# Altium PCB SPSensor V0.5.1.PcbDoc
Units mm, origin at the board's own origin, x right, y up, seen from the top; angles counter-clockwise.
Board outline 22.01 x 74 mm, 4 copper layers (TopLayer, GND, PWR, BottomLayer); 82 components, 57 nets, 274 pads, 109 vias.
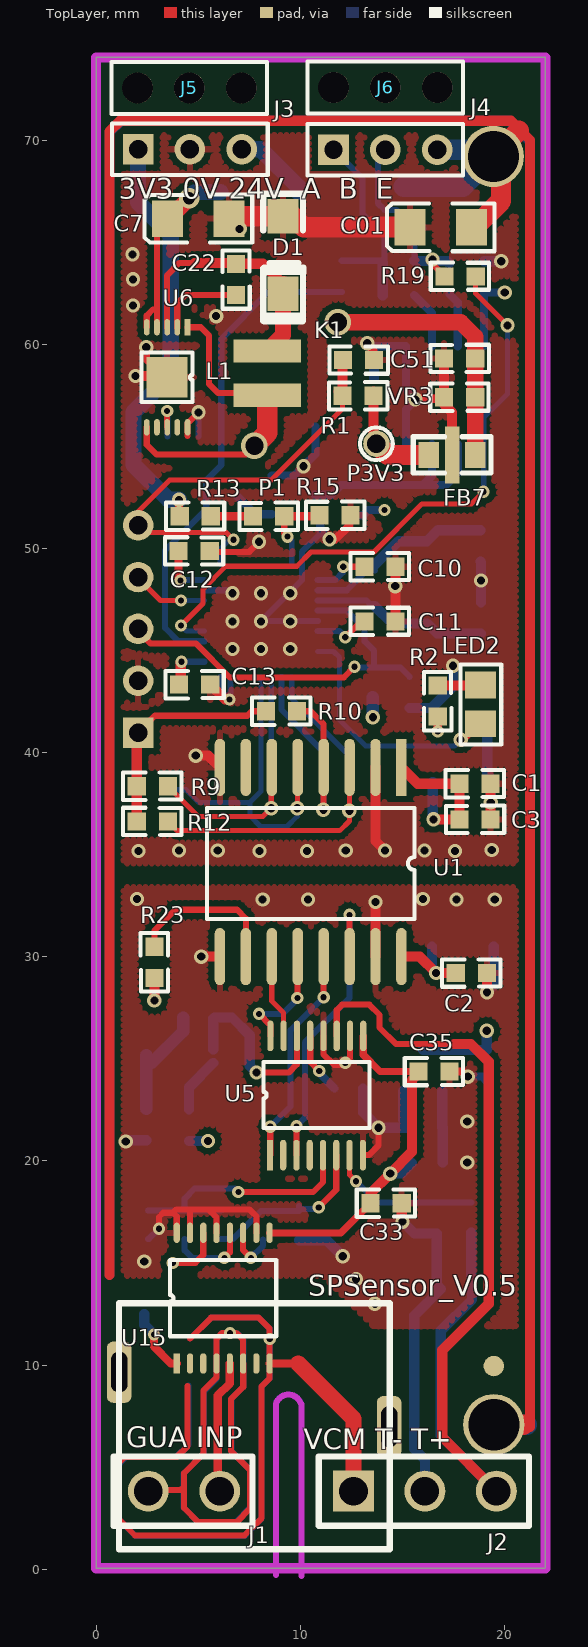
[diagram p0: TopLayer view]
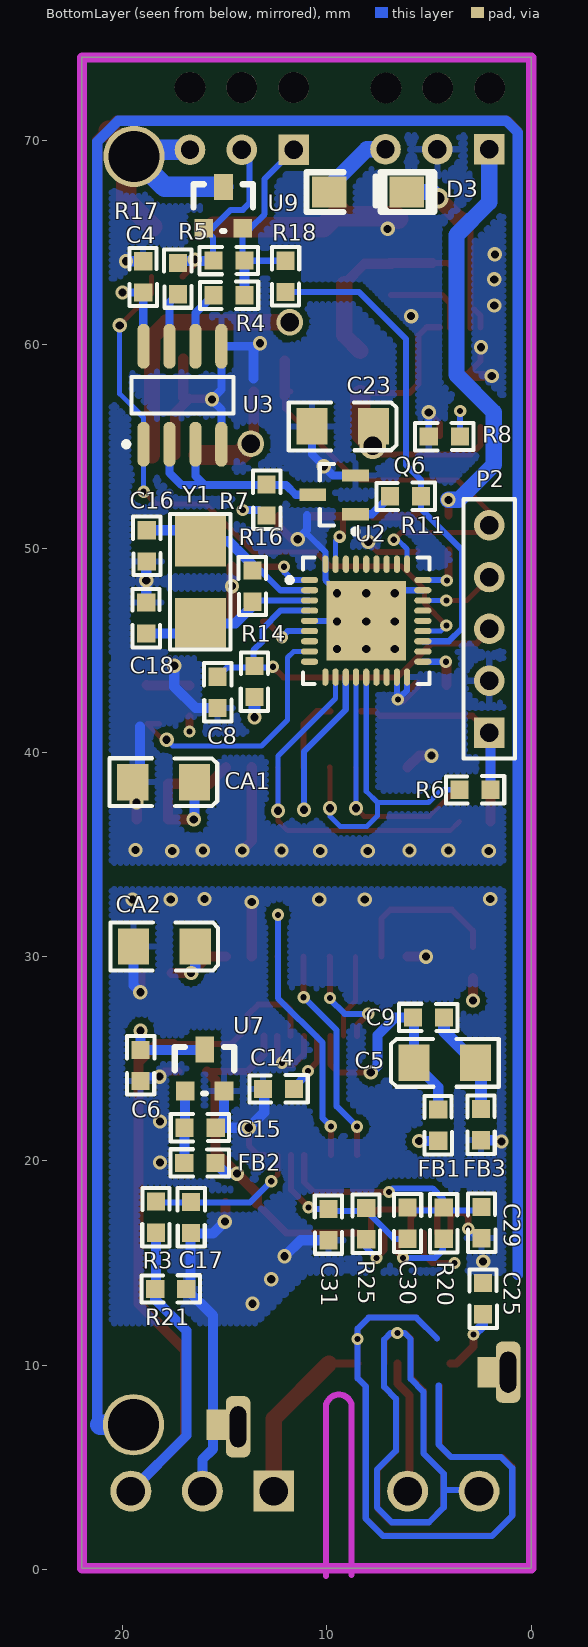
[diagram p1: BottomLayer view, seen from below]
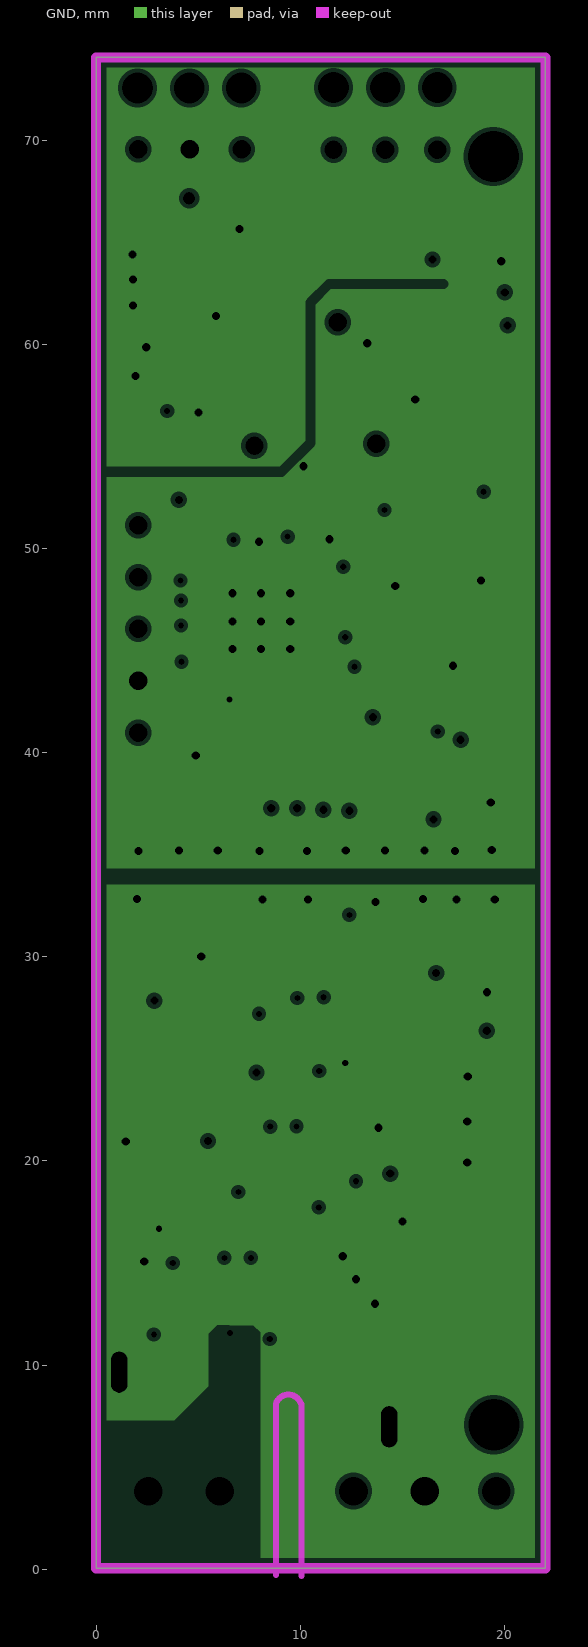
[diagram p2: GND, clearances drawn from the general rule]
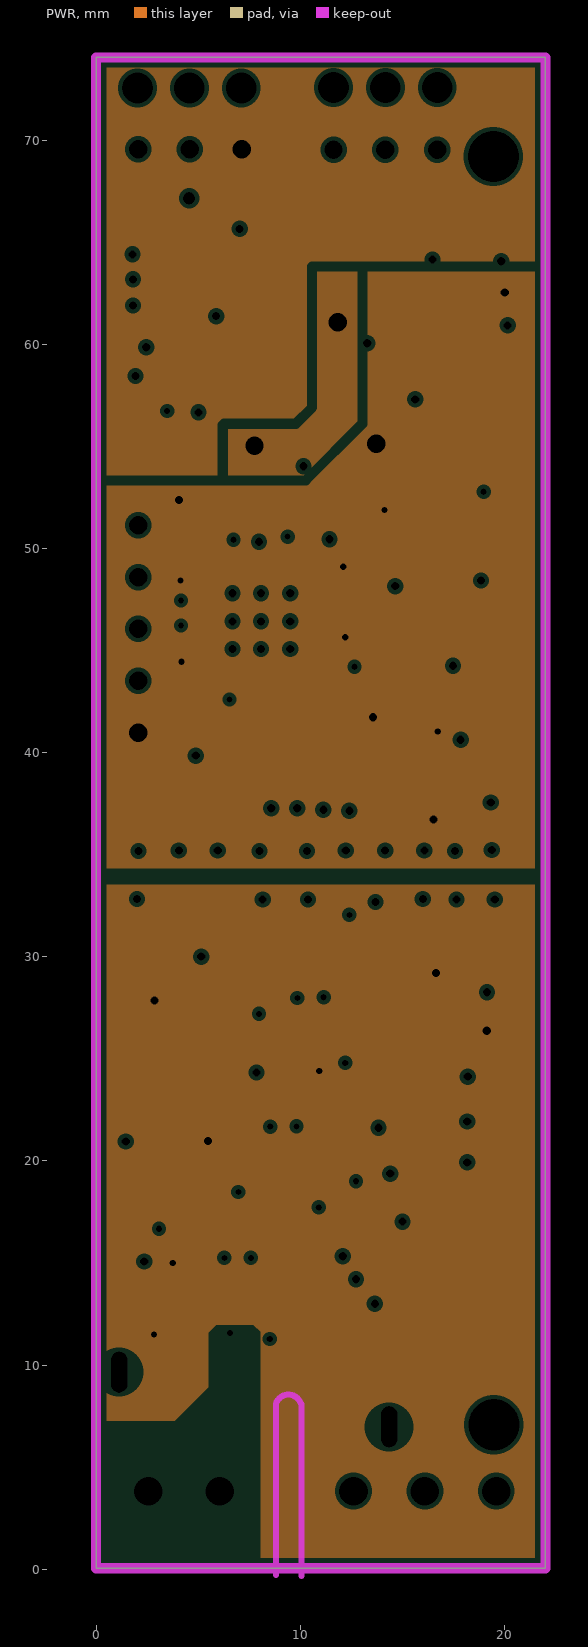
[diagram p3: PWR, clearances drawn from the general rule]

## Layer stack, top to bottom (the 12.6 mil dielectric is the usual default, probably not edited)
TopLayer: signal copper 0.0356
Dielectric: core 0.32, FR-4, Dk 4.8
GND: plane copper 0.0356, net (Multiple Nets)
Dielectric: prepreg 0.32, FR-4, Dk 4.8
PWR: plane copper 0.0356, net (Multiple Nets)
Dielectric: core 0.32, FR-4, Dk 4.8
BottomLayer: signal copper 0.0356

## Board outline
-0.006,0.05 22,0.05 22,74.05 -0.006,74.05

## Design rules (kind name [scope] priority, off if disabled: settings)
Clearance Clearance_poly [InPolygon] p1: gap=0.3
Clearance [All] p2: gap=0.15
ComponentClearance [All] p1: gap=0.15 collisioncheckmode=3 verticalgap=0.254 showdistances=FALSE
FabricationTestPointUsage TestPointUsage [All] p1: valid=0 allowmultiple=FALSE
FabricationTestpoint Testpoint [All] p1: side=3 testpointundercomponent=TRUE minsize=1.016 maxsize=2.54 preferedsize=1.524 minholesize=0.508 maxholesize=1.016 preferedholesize=0.813 testpointgrid=0.025 allowsidetop=TRUE allowsidebottom=TRUE usegrid=TRUE gridtolerance=0
HoleSize [All] p1: absolutevalues=TRUE maxlimit=10 minlimit=0.025 maxpercent=80.000 minpercent=20.000
MinimumSolderMaskSliver [All] p1: minsoldermaskwidth=0.15
PlaneClearance [All] p1: clearance=0.2
PlaneConnect [All] p1: planeconnectstyle=Relief reliefexpansion=0.3 reliefentries=4 reliefconductorwidth=0.3 reliefairgap=0.3
PolygonConnect PolygonConnect_via [IsVia] p1: connectstyle=Direct reliefconductorwidth=0.254 reliefentries=4 polygonreliefangle="90 Angle"
PolygonConnect [All] p2: connectstyle=Relief reliefconductorwidth=0.3 reliefentries=4 polygonreliefangle="90 Angle"
RoutingVias [All] p1: holewidth=0.305 width=0.61 viastyle="Through Hole" minholewidth=0.254 minwidth=0.508 maxholewidth=2 maxwidth=5
SilkToSilkClearance [All] p1: silktosilkclearance=0
SilkscreenOverComponentPads [All] p1: minsilkscreentomaskgap=0
SolderMaskExpansion [All] p1: expansion=0.102
Width [All] p1: maxlimit=5.08 minlimit=0.1 preferedwidth=0.254
19 further rules are at their usual default settings.

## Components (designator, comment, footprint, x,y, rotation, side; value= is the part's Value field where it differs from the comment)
C1 "10nF" SM0603 18.55,38.525 r0 top
C01 "1nF/2kV" SM1206 16.875,65.725 r180 top
C2 "0.1uF" SM0603 18.375,29.25 r0 top
C3 "0.1uF" SM0603 18.55,36.675 r180 top
C4 "0.1uF" SM0603 19.05,63.3 r90 bottom
C5 "10uF" SM1206 4.225,24.8 r0 bottom
C6 "4.7uF" SM0603 19.075,24.675 r270 bottom
C7 "4.7uF/50V" SM1206 5,66.15 r180 top
C8 "0.1uF" SM0603 15.3,42.95 r270 bottom
C9 "0.1uF" SM0603 5.025,27.075 r180 bottom
C10 "0.1uF" SM0603 13.9,49.15 r0 top
C11 "0.1uF" SM0603 13.9,46.475 r0 top
C12 "0.1uF" SM0603 4.8,49.925 r0 top
C13 "0.1uF" SM0603 4.825,43.375 r0 top
C14 "0.1uF" SM0603 12.375,23.475 r0 bottom
C15 "1uF" SM0603 16.21,21.675 r180 bottom
C16 "22pF" SM0603 18.775,50.125 r270 bottom
C17 "1uF" SM0603 16.6,17.225 r270 bottom
C18 "22pF" SM0603 18.9,46.59 r90 bottom
C22 "0.47uF" SM0603 6.8,63.175 r90 top
C23 "22uF" SM1206 9.225,55.975 r180 bottom
C25 "0.1uF" SM0603 2.4,13.25 r90 bottom
C29 "1uF" SM0603 2.475,16.975 r90 bottom
C30 "100pF" SM0603 6,16.95 r270 bottom
C31 "1uF" SM0603 9.875,16.875 r270 bottom
C33 "0.1uF" SM0603 14.2,17.975 r0 top
C35 "0.1uF" SM0603 16.55,24.425 r0 top
C51 "0.1uF" SM0603 17.8,59.25 r180 top
CA1 "10uF" SM1206 18,38.55 r180 bottom
CA2 "10uF" SM1206 17.96,30.5 r180 bottom
D1 "CD1607-B140" 1206D 9.15,66.075 r270 top
D3 "M7" 1206D 9.7,67.45 r180 bottom
FB1 "BLM18PG600SN1" SM0603 4.6,21.75 r90 bottom
FB2 "BLM18PG600SN1" SM0603 16.225,19.95 r180 bottom
FB3 "BLM18PG600SN1" SM0603 2.5,21.775 r90 bottom
FB7 "NFM21PC105B1C3" NFM21PC105 18.575,54.575 r180 top
J1 "Header 4" CON1x2-3.5mm 2.55,3.825 r0 top
J2 "Header 2" CON1x3-3.5mm 12.6,3.825 r0 top
J3 "Header 3" HDR1X3#1 2.05,69.55 r0 top
J4 "Header 3" HDR1X3#1 11.625,69.525 r0 top
J5 "Header 3" HDR1X3#2 2.025,72.55 r0 top
J6 "Header 3" HDR1X3#2 11.625,72.575 r0 top
K1 "KEY1" SM0603 12.85,59.175 r180 top (schematic designator R1)
L1 "LPS3010-472ML" LPS3010 8.375,59.666 r270 top
LED2 "RUN" SM0805 18.8,42.375 r270 top
P1 "NC" sm0603 8.45,51.525 r180 top
P2 "Header 5" HDR1X5 2.05,40.975 r90 bottom
P3V3 "TestPoint" "test point" 13.725,55.125 r90 top
Q6 "MMBT3904" SOT23_N 9.65,52.625 r0 bottom
R1 "10K" SM0603 12.825,57.425 r180 top
R2 "560R" SM0603 16.675,42.525 r90 top
R3 "10K" SM0603 18.425,17.24 r90 bottom
R4 "10R" SM0603 14.8,62.35 r0 bottom
R5 "120R" SM0603 14.8,64.15 r180 bottom
R6 "100K" SM0603 2.75,38.125 r0 bottom
R7 "4.7K" SM0603 12.9,52.375 r270 bottom
R8 "49.9K" SM0603 4.25,55.525 r180 bottom
R9 "100K" SM0603 2.75,38.4 r0 top
R10 "100K" SM0603 9.075,42.075 r0 top
R11 "1K" SM0603 6.15,52.5 r0 bottom
R12 "100K" SM0603 2.75,36.675 r0 top
R13 "1K" SM0603 4.85,51.625 r0 top
R14 "10K" SM0603 13.6,43.475 r90 bottom
R15 "100K" SM0603 11.7,51.575 r180 top
R16 "10M" SM0603 13.6,48.15 r270 bottom
R17 "10R" SM0603 17.25,63.21 r270 bottom
R18 "0R" SM0603 11.975,63.325 r270 bottom
R19 "0R" SM0603 17.825,63.375 r0 top
R20 "10K" SM0603 4.325,16.95 r90 bottom
R21 "NC" SM0603 17.65,13.675 r0 bottom
R23 "4.7K" SM0603 2.9,29.725 r270 top
R25 "10K" SM0603 8.125,16.925 r90 bottom
U1 "ADuM5401ARWZ" ADUM1401 14.95,39.275 r270 top
U2 "STM32F103T8U6" VFQN36_V 8.075,46.45 r180 bottom
U3 "MAX3485CSA" NSO8_N 17.075,57.5 r90 bottom
U5 "AD7793BRU" AD7793 10.795,23.2 r90 top
U6 "LT3971IMSE-3.3" LT3971 3.475,58.381 r180 top
U7 "AD1584BRTZ" SOT-23 14.614,25.575 r180 bottom
U9 "SM712.TCT" SOT-23 13.7,67.825 r180 bottom
U15 "LMP91200" LMP91200 6.219,13.275 r0 top
VR3 "V3.5MLA0603N" SM0603 17.8,57.45 r0 top (schematic designator VA2)
Y1 "8MHz" CY5.4X4.6 16.2,50.325 r270 bottom

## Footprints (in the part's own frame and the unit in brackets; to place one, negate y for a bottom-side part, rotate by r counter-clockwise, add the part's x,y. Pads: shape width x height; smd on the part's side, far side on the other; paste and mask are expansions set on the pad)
1206D [mm]
  rect 1.7x1.524 smd: 1(-0.19,0.003) 2(3.61,0.003)
  silkscreen extent -1.3,-0.97 4.96,0.99
AD7793 [mm]
  rect 1.5x0.3 smd: 1(-2.921,2.286)
  oval 1.5x0.3 smd: 2(-2.921,1.636) 3(-2.921,0.986) 4(-2.921,0.336) 5(-2.921,-0.314) 6(-2.921,-0.964) 7(-2.921,-1.614) 8(-2.921,-2.264) 9(2.921,-2.286) 10(2.921,-1.636) 11(2.921,-0.986) 12(2.921,-0.336) 13(2.921,0.314) 14(2.921,0.964) 15(2.921,1.614) 16(2.921,2.264)
  silkscreen extent -1.59,-2.59 1.64,2.61
ADUM1401 [mm]
  rect 2.8x0.51 smd: 1(0,0)
  oval 2.8x0.51 smd: 2(0,-1.27) 3(0,-2.54) 4(0,-3.81) 5(0,-5.08) 6(0,-6.35) 7(0,-7.62) 8(0,-8.89) 9(9.271,-8.89) 10(9.271,-7.62) 11(9.271,-6.35) 12(9.271,-5.08) 13(9.271,-3.81) 14(9.271,-2.54) 15(9.271,-1.27) 16(9.271,0)
  silkscreen extent 1.99,-9.53 7.43,0.64
CON1x2-3.5mm [mm]
  round 2 hole 1.4: 1(0,0) 2(3.5,0)
  silkscreen extent -1.7,-1.7 5.1,1.7
CON1x3-3.5mm [mm]
  rect 2x2 hole 1.4: 1(0,0)
  round 2 hole 1.4: 2(3.5,0) 3(7,0)
  silkscreen extent -1.7,-1.7 8.6,1.7
CY5.4X4.6 [mm]
  rect 2.5x2.5 smd: 1(-0.025,0) 2(4,0)
  silkscreen extent -1.35,-1.49 5.28,1.49
HDR1X3#1 [mm] "Connector; Header; 3 Position"
  rect 1.5x1.5 hole 0.9: 1(0,0)
  round 1.5 hole 0.9: 2(2.54,0) 3(5.08,0)
  silkscreen extent -1.27,-1.27 6.35,1.27
HDR1X3#2 [mm] "Connector; Header; 3 Position"
  round 1.5 hole 1.5: 1(0,0) 2(2.54,0) 3(5.08,0)
  silkscreen extent -1.27,-1.27 6.35,1.27
HDR1X5 [mm] "Connector; Header; 5 Position"
  rect 1.5x1.5 hole 0.9: 1(0,0)
  round 1.5 hole 0.9: 2(2.54,0) 3(5.08,0) 4(7.62,0) 5(10.16,0)
  silkscreen extent -1.27,-1.27 11.43,1.27
LMP91200 [mm]
  rect 0.3x1 smd: 1(-2.275,-3.2)
  oval 0.3x1 smd: 2(-1.625,-3.2) 3(-0.975,-3.2) 4(-0.325,-3.2) 5(0.325,-3.2) 6(0.975,-3.2) 7(1.625,-3.2) 8(2.275,-3.2) 9(2.275,3.2) 10(1.625,3.2) 11(0.975,3.2) 12(0.325,3.2) 13(-0.325,3.2) 14(-0.975,3.2) 15(-1.625,3.2) 16(-2.275,3.2)
  silkscreen extent -2.6,-1.87 2.6,1.87
LPS3010 [mm]
  rect 1.14x3.3 smd: 1(0,0) 2(2.16,0)
LT3971 [mm]
  rect 0.28x0.8 smd: 1(-1,-2.45)
  oval 0.28x0.8 smd: 2(-0.5,-2.45) 3(0,-2.45) 4(0.5,-2.45) 5(1,-2.45) 6(1,2.45) 7(0.5,2.45) 8(0,2.45) 9(-0.5,2.45) 10(-1,2.45)
  rect 2x2 smd: 11(0,0)
  silkscreen extent -1.25,-1.21 1.25,1.22
NFM21PC105 [mm]
  rect 1x1.27 smd: 1(0.01,0.008) 2(2.286,0)
  rect 0.7x2.8 smd: 3(1.143,0)
  silkscreen extent -0.76,-0.89 3.05,0.89
NSO8_N [mm] "SOIC, 8-Leads, Body 4.9x3.9mm, Pitch 1.27mm, IPC Medium Density"
  oval 2.2x0.6 smd: 1(-2.4,1.905) 2(-2.4,0.635) 3(-2.4,-0.635) 4(-2.4,-1.905) 5(2.4,-1.905) 6(2.4,-0.635) 7(2.4,0.635) 8(2.4,1.905)
  silkscreen extent -2.52,-2.5 0.9,2.88, body extent -2,-2.5 2,2.5, height 1.75
SM0603 [mil]
  rect 35x35 smd: 1(-30,-2) 2(30,-2)
  silkscreen extent -57,-28 56,24
sm0603 [mil]
  rect 35x35 smd: 1(-30,-2) 2(30,-2)
  silkscreen extent -57,-28 56,24
SM0805 [mm]
  rect 1.3x1.5 smd: 1(-0.933,0.022) 2(0.967,0.022)
  silkscreen extent -1.93,-0.97 1.98,1.04
SM1206 [mil]
  rect 60x70 smd: 1(59.5,0) 2(-59.5,0)
  silkscreen extent -104,-46 104,46
SOT23_N [mm] "SOT23, 3-Leads, Body 2.9x1.3mm, Pitch 0.95mm, Lead Span 2.3mm, IPC Medium Density"
  rect 1.3x0.6 smd: 1(-1.05,0.95) 2(-1.05,-0.95) 3(1.05,0)
  silkscreen extent -1.17,-1.5 0.7,1.92, body extent -0.7,-1.5 0.7,1.5, height 1.1
SOT-23 [mil]
  rect 36x36 smd: 1(-91.86,-84.66) 2(-16.86,-84.66)
  rect 36x50 smd: 3(-53.86,-4.66)
  silkscreen extent -112,-90 3,0
"test point" [mm]
  round 1.3 hole 0.9: 1(0,0)
  silkscreen extent -0.8,-0.8 0.8,0.8
VFQN36_V [mm] "QFN, 36-Leads, Body 6x6mm, Pitch 0.5mm, ST Recommended"
  oval 0.85x0.3 smd: 1(-2.775,2) 2(-2.775,1.5) 3(-2.775,1) 4(-2.775,0.5) 5(-2.775,0) 6(-2.775,-0.5) 7(-2.775,-1) 8(-2.775,-1.5) 9(-2.775,-2) 19(2.775,-2) 20(2.775,-1.5) 21(2.775,-1) 22(2.775,-0.5) 23(2.775,0) 24(2.775,0.5) 25(2.775,1) 26(2.775,1.5) 27(2.775,2)
  oval 0.3x0.85 smd: 10(-2,-2.755) 11(-1.5,-2.755) 12(-1,-2.755) 13(-0.5,-2.755) 14(0,-2.755) 15(0.5,-2.755) 16(1,-2.755) 17(1.5,-2.755) 18(2,-2.755) 28(2,2.775) 29(1.5,2.775) 30(1,2.775) 31(0.5,2.775) 32(0,2.775) 33(-0.5,2.775) 34(-1,2.775) 35(-1.5,2.775) 36(-2,2.775)
  rect 3.9x3.9 smd: 37(0,0)
  silkscreen extent -3.88,-3.1 3.1,3.1, body extent -3.05,-3.05 3.05,3.05, height 1

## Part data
C1 C01 C6 C7 C9 C14 C15 C17 C22 C25 C29 C30 C31 C33 C35 C51: library part CAP, "Capacitor"
C2 C3: library part CA, "电?"
C4 C8: library part Cap, "Capacitor, X7R Ceramic"
C5: library part C, "极?"
C10 C11 C12 C13 C16 C18: library part Cap, "Capacitor"
C23: library part CAPE, "极?"
CA1 CA2: library part CAPE, "Capacitor"
D1: library part DIODE, "Diode"
D3: library part "Diode 1N4007", "1 Amp General Purpose Rectifier"
FB1 FB3 L1: library part INDUCTOR
FB2 FB7: library part Inductor, "Inductor"
J1: "Header, 4-Pin"
J2: "Header, 2-Pin"
J3 J4 J5 J6: "Header, 3-Pin"
K1: library part "Header 2", "Header, 2-Pin"
LED2: library part LED0, "Typical INFRARED GaAs LED"
P1: library part H, "Header, 2-Pin, 2.54mm, 排?"
P2: "Header, 5-Pin"
Q6: "NPN Switching Transistor"
R1 R2 R4 R5 R7 R11 R16 R17 R18 R19: library part Res2, "Resistor"
R3 R6 R9 R10 R12 R20 R21 R25: library part RES, "电?"
R8 R13 R14 R15 R23: library part RE, "电?"
U1: library part ADUM1401, "1Mbps Data Rate, 100ns Propagation delay"
U2: "STM32 ARM-based 32-bit MCU with 64 Kbytes Flash, 36-pin VFQFPN, Industrial Temperature"
U3: library part MAX485CSA, "Low-Power, Slew-Rate-Limited RS-485/RS-422 Transceiver"
U5: library part AD7793
U6: library part LT3971
U7: library part "Header 3", "4.096V reference"
U9: library part "Header 3", "Asymmerical TVS Diode for RS485"
VR3: library part "D Zener", "Zener Diode"
Y1: library part XTAL, "Crystal Oscillator"

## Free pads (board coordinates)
  rrect50% 1.2x3 hole 0.8 slot 2 at 90 deg: 0(1.125,9.65) 0(14.35,6.975)
  round 1 smd: 0(19.475,9.95)
  rect 1x1.5 smd far side: 1(2.125,9.65) 1(15.4,7.075)
  round 3 hole 2.5: ""(19.45,69.2) ""(19.475,7.075)

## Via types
v1: diameter 0.7, hole 0.4, TopLayer to BottomLayer, 74 vias
v2: diameter 0.6, hole 0.3, TopLayer to BottomLayer, 32 vias
v3: diameter 1.3, hole 0.9, TopLayer to BottomLayer, 2 vias
v4: diameter 1, hole 0.6, TopLayer to BottomLayer, 1 vias

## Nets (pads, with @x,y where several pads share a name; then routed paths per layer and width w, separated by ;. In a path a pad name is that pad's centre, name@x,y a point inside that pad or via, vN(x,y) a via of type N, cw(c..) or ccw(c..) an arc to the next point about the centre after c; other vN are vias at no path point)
+24V: D3.1 J3.3 | length 3.8
  BottomLayer w0.8: J3.3 8.05,69.55 9.89,67.71 D3.1
BOOT0: P1.1 R15.2 U2.35 | length 4.3
  TopLayer w0.3: P1.1 9.212,50.738 v2(9.375,50.575)
  TopLayer w0.4: P1.1@9.262,51.576 R15.2@10.977,51.576
  BottomLayer w0.25: v2(9.375,50.575) 9.575,50.375 U2.35
  BottomLayer w0.3: v2(9.375,50.575) v2@9.375,50.675
DVDD: C5.1 C9.1 FB1.2 U5.14 | length 12
  TopLayer w0.3: v1(7.85,24.325) 9.425,24.325 9.831,24.731 U5.14
  BottomLayer w0.5: FB1.2 4.549,23.613 C5.1 ; C5.1@5.736,25.45 5.736,26.973 C9.1 6.651,27.024 7.525,26.15 7.525,24.65 v1(7.85,24.325)
EARTH: C01.2 J4.3 pad. U9.3 | length 297.4
  TopLayer w0.5: 0.644,14.425 0.644,70.419 1.175,70.95 20.3,70.95 21.25,70 21.25,6.975
  TopLayer w1: C01.2@18.561,65.75 19.825,67.014 pad.@19.825,69.45 ; pad.@19.45,69.2 20.7,70.45 ; pad.@19.475,7.075 pad.@20.925,7.075
  BottomLayer w0.5: 0.65,14.425 0.65,70.375 1.225,70.95 15.975,70.95 ; 15.968,70.943 15.975,70.95 ; 21.25,6.975 21.25,69.925 20.225,70.95 15.975,70.95
  BottomLayer w1: U9.3 17.957,67.707 19.45,69.2 19.125,69.525 J4.3 ; pad.@19.475,7.075 21.1,7.075
GND: C01.1 C1.2 C3.1 C4.2 C7.2 C8.2 C10.2 C11.2 C12.2 C13.2 C16.2 C18.2 C23.2 C51.2 CA1.2 D1.1 FB7.3 J3.2 K1.1 P2.2 Q6.2 R8.1 R15.1 U1.2 U1.8 U2.5 U2.17 U2.18 U2.26 U2.36 U2.37 U3.4 U3.5 U6.10 U6.11 VR3.1 | length 76.9
  TopLayer w0.3: v1@2.475,59.85 2.475,59.191 U6.11@3.225,58.441 ; 4.475,55.506 U6.10 4.475,56.125 v1(5.012,56.662) ; C12.2 5.611,49.825 7.5,49.825 7.975,50.3 v1(7.975,50.325)
  TopLayer w0.4: D1.1@9.153,66.74 D1.1@9.544,66.349 ; v1(11.425,50.45) 11.725,50.45 12.375,51.1 R15.1@12.375,51.575 ; v1@13.25,60.025 13.587,59.688 K1.1@13.587,59.199 ; v1@15.625,57.325 VR3.1@16.762,57.325
  TopLayer w0.5: v1@1.887,58.441 v1(1.925,58.441) 3.225,58.441 U6.11@3.469,58.441 ; v1(4.875,39.85) 5.485,39.85 U1.8 ; C13.2 6.311,42.6 v2(6.525,42.6) ; U1.2 13.68,35.67 v1(14.15,35.2) ; C11.2 C10.2 ; VR3.1@16.762,57.325 17.432,56.655 FB7.3 ; VR3.1 C51.2 ; C3.1 C1.2
  TopLayer w1: C7.2 6.627,66.265 D1.1 9.628,66.265 10.168,65.725 C01.1 ; 13.525,65.75 C01.1@15.539,65.75
  BottomLayer w0.3: R8.1 v1(5.012,56.662) ; U2.26 U2.37@6.575,47.95 ; U2.18 6.075,43.05 v2(6.525,42.6) 6.575,42.65 U2.17 ; U2.5 U2.37 10.075,48.45 U2.36 10.075,49.825 10.975,50.725 10.975,50.9
  BottomLayer w0.4: Q6.2 9.7,53.575 v1(10.15,54.025) 10.736,54.611 C23.2 ; 10.975,51.625 10.975,50.9 v1(11.425,50.45) ; v1@13.425,59.9 U3.5 15.17,57.78 15.663,57.288 15.65,57.275 15.17,56.795 U3.4
  BottomLayer w0.5: v1(13.275,60.05) 13.425,59.9 13.602,59.723 13.602,58.326 ; C8.2 16.438,42.188 17.475,43.225 v1(17.475,44.25) ; C16.2 18.849,49.34 v1(18.849,48.425) C18.2 ; C4.2 v1(19.838,64.062) ; 19.151,41.263 19.151,38.91 CA1.2 19.325,38.364 v1(19.325,37.55)
  other v1: 2.075,35.175 8,35.175 10.325,35.175 17.575,35.175 4.05,35.2 5.95,35.2 12.225,35.2 16.075,35.2 19.375,35.225 6.675,45.075 8.075,45.075 9.5,45.075 6.675,46.425 8.075,46.425 9.5,46.425 6.675,47.8 8.075,47.8 9.5,47.8 14.65,48.15 15.625,57.3 2.45,59.85 5.875,61.375 1.8,61.9 1.8,63.175 1.775,64.4 7.025,65.65
GND_ISO: C2.2 C6.2 C14.2 C15.2 C17.2 C25.2 C29.1 C31.2 C33.2 C35.2 CA2.2 FB3.1 J2.2 pad.0@1.125,9.65 pad.0@14.35,6.975 pad.1 R21.1 U1.9 U1.15 U5.8 U5.10 U5.12 U7.2 U15.10 U15.13 U15.15 U15.16 | length 50.8
  TopLayer w0.3: v2(3.075,16.676) 3.075,17.25 3.283,17.458 3.758,17.458 ; U15.16 3.944,17.272 3.758,17.458 ; U15.15 4.594,17.55 4.519,17.625 ; U15.13 5.894,17.225 5.494,17.625 ; U15.10 7.844,17.28 7.5,17.625 5.494,17.625 ; U5.12 11.131,25.219 11.65,24.7 12.1,24.7 12.431,25.031 U5.10 ; U5.8 13.354,20.279 13.825,20.75 v1(13.825,21.625) ; 3.758,17.458 3.925,17.625 4.519,17.625 ; 4.519,17.625 5.494,17.625
  TopLayer w0.4: C35.2@17.272,24.375 17.95,24.375 v1(18.2,24.125)
  TopLayer w0.5: v1(5.146,30.004) U1.9 ; U1.15 v1(13.68,32.68) ; v1@14.925,17.025 v1@14.962,17.025 ; C33.2 v1@14.962,17.025 ; v1(15,17.025) v1@14.962,17.025 ; v1(19.137,28.263) C2.2
  BottomLayer w0.3: C29.1@2.55,16.178 2.577,16.178 v2(3.075,16.676)
  BottomLayer w0.4: v1(18.2,24.125) 18.914,24.125 C6.2
  BottomLayer w0.5: v1(1.45,20.951) 1.512,21.013 FB3.1 ; C31.2 11.287,16.113 v1(12.075,15.325) ; C14.2@13.072,23.55 13.072,22.378 v1(13.825,21.625) C15.2 ; v1(15,17.025) 15.587,16.438 16.676,16.438 16.676,13.938 R21.1 15.575,12.413 15.575,5.9 16.1,5.375 J2.2 ; U7.2 15.042,22.03 C15.2 ; C15.2 C15.2 ; v1(19.137,28.263) 19.472,28.598 CA2.2
  other v1: 13.65,13 12.725,14.2 2.35,15.075 18.175,19.925 18.175,21.925 8.15,32.8 10.375,32.8 17.65,32.8 19.519,32.8 2,32.825 16,32.825
  other v2: 12.2,24.8
GUARD: J1.1 U15.4 U15.6 | length 49.1
  TopLayer w0.3: J1.1@2.95,3.875 4.125,3.875 4.3,4.05 ; U15.6 7.194,11.23 6.85,11.575 v2(6.55,11.575) 6.175,11.575 5.894,11.295 U15.4 5.894,9.394 5.25,8.75 5.25,5.65 4.3,4.7 4.3,4.05 ; U15.6@7.2,10.075 7.2,8.925 6.6,8.325 6.6,5.8 7.525,4.875 7.525,2.95 6.875,2.3 5,2.3 4.3,3 4.3,4.05
  BottomLayer w0.3: J1.1@2.95,3.875 4.225,3.875 ; 4.275,3.025 5,2.3 6.825,2.3 7.55,3.025 7.55,4.875 6.625,5.8 6.625,8.35 7.2,8.925 7.2,11.25 6.875,11.575 v2(6.55,11.575) 6.2,11.575 5.9,11.275 5.9,9.325 5.275,8.7 5.275,5.675 4.275,4.675 4.275,3.025
JNTRST: 
JTCK: K1.2 P2.5 R1.2 U2.28 | length 22
  TopLayer w0.25: v2(6.725,50.425) 6.375,50.775 2.41,50.775 P2.5 2.05,51.8 3.6,53.35 8.575,53.35 12.063,56.838 R1.2
  TopLayer w0.3: R1.2@11.776,57.676 R1.2@12.063,57.676
  TopLayer w0.5: R1.2 12.063,57.676 K1.2@12.063,59.199
  BottomLayer w0.25: U2.28 6.075,49.975 6.525,50.425 v2(6.725,50.425)
JTDI: U2.29
JTDO: U2.30
JTMS: P2.4 U2.25 | length 3.8
  TopLayer w0.25: P2.4@2,48.6 3.15,47.45 v2(4.15,47.45)
  BottomLayer w0.25: v2(4.15,47.45) U2.25
JTRST: U2.31
LED_S1: U2.23
LED_S2: LED2.2 U2.8 | length 12.7
  TopLayer w0.25: v1(17.85,40.625) 18.039,40.625 LED2.2 LED2.2@18.208,41.408
  BottomLayer w0.25: U2.8 11.625,44.95 11.925,44.65 11.925,41.6 13.2,40.325 17.55,40.325 v1(17.85,40.625)
MCU_RXD1: R19.2 U2.22 U3.1 | length 30.9
  TopLayer w0.25: v2(4.15,46.225) 5.225,47.3 5.225,48 6.35,49.125 9.825,49.125 10.525,49.825 13.6,49.825 15.95,52.175 18.375,52.175 v2(18.975,52.775) ; R19.2 18.587,62.488 v1(20.15,60.925)
  BottomLayer w0.25: v2(4.15,46.225) 4.425,45.95 U2.22 ; v2(18.975,52.775) 18.98,52.78 U3.1 18.98,56.405 20.15,57.575 v1(20.15,60.925)
MCU_TXD1: R11.1 R18.2 U2.21 | length 24.3
  BottomLayer w0.3: U2.21 4.025,45.45 3.375,46.1 3.375,49.9 5.388,51.913 R11.1 5.388,53.338 6.125,54.075 6.125,60.25 8.438,62.563 R18.2
MISO1: R9.2 U1.6 U2.13 | length 14.5
  TopLayer w0.25: R9.2 4.986,36.875 8.175,36.875 v1(8.575,37.275) ; v1@8.575,37.15 v1(8.575,37.275) ; U1.6 8.575,39.25 v1(8.575,37.275)
  BottomLayer w0.25: v1@8.575,37.15 v1(8.575,37.275) U2.13
MOSI1: R6.2 U1.5 U2.14 | length 16.5
  TopLayer w0.25: v1(9.85,37.275) 9.85,39.255 U1.5 U1.5@9.862,39.283
  BottomLayer w0.25: R6.2 4.399,38.176 5.025,37.55 7.525,37.55 ; U2.14 8.075,38.1 7.525,37.55 ; v1(9.85,37.275) 9.85,36.875 9.35,36.375 8.05,36.375 7.525,36.9 7.525,37.55
NetC5_2: C5.2 C9.2 FB3.2 | length 5.5
  BottomLayer w0.6: FB3.2 2.449,24.699 C5.2@2.45,25.186 ; C5.2 4.263,26.349 C9.2
NetC7_1: C7.1 D3.2 U6.4 U6.5 | length 9.9
  TopLayer w0.3: U6.5 2.475,61.4 2.775,61.7 2.969,61.7 ; U6.4@2.969,60.799 2.969,61.7 ; C7.1 3.489,66.114 2.969,65.594 2.969,61.7
  TopLayer w0.8: C7.1 3.55,66.15 v4(4.55,67.15)
  BottomLayer w0.8: v4(4.55,67.15) 4.853,67.453 D3.2
NetC15_1: C15.1 FB2.1 U7.1 | length 3.5
  BottomLayer w0.5: U7.1 16.947,21.649 C15.1 FB2.1@16.972,19.914
NetC16_1: C16.1 R16.1 U2.2 Y1.1 | length 9.1
  BottomLayer w0.3: U2.2 12.275,47.95 13.237,48.912 R16.1
  BottomLayer w0.5: R16.1@13.651,49.201 14.8,50.35 Y1.1 16.737,50.887 C16.1
NetC17_1: C17.1 R3.2 U5.7 | length 7.5
  TopLayer w0.25: U5.7 12.409,19.316 v2(12.725,19)
  BottomLayer w0.3: v2(12.725,19) 13.763,17.962 R3.2@18.374,17.962
NetC18_1: C18.1 R16.2 U2.3 Y1.2 | length 8.7
  BottomLayer w0.3: U2.3 13.235,47.45 13.423,47.262 R16.2@13.651,47.262
  BottomLayer w0.5: R16.2@13.651,47.162 14.488,46.325 Y1.2 ; Y1.2@16.163,46.288 Y1.2 ; C18.1 16.697,45.828 Y1.2
NetC22_1: C22.1 U6.2 | length 4.3
  TopLayer w0.3: U6.2@3.969,60.799 3.969,62 4.382,62.413 C22.1
NetC22_2: C22.2 D1.2 L1.1 U6.3 | length 12.6
  TopLayer w0.3: U6.3@3.469,60.799 3.469,63.375 4.077,63.983 4.825,63.983
  TopLayer w0.5: 4.825,63.983 C22.2@6.925,63.983 ; C22.2 8.156,63.937 D1.2@9.153,62.94
  TopLayer w0.8: L1.1 9.153,60.443 D1.2@9.153,62.94
NetC23_1: C23.1 C51.1 FB7.1 L1.2 U6.1 U6.6 VR3.2 | length 28.7
  TopLayer w0.3: U6.6 2.475,55.075 2.95,54.6 7.325,54.6 v3(7.75,55.025) ; U6.1 5.119,60.831 5.525,60.425 5.525,58.05 5.969,57.606 L1.2@8.375,57.606
  TopLayer w0.8: v3(11.825,61.075) 17.85,61.075 18.562,60.363 C51.1 18.565,59.298 FB7.1
  TopLayer w1: v3(7.75,55.025) 8.375,55.65 L1.2
NetC29_2: C29.2 C30.1 R20.2 U5.5 | length 12.7
  TopLayer w0.3: v2(6.962,18.475) 10.625,18.475 11.109,18.959 U5.5
  BottomLayer w0.3: C29.2@2.55,17.575 R20.2@4.325,17.575 ; C30.1@6.1,17.575 R20.2@4.325,17.575 ; v2(6.962,18.475) 6.787,18.65 4.825,18.65 4.325,18.15 R20.2@4.325,17.575
NetC30_2: C30.2 C31.1 R25.2 U5.6 | length 8.6
  TopLayer w0.3: v2(10.9,17.725) 11.759,18.584 U5.6
  BottomLayer w0.3: C30.2@6.1,16.178 6.703,16.178 8.075,17.55 9.922,17.55 9.925,17.547 C31.1@9.925,17.792 ; C31.1 10.812,17.637 v2(10.9,17.725)
NetLED2_1: LED2.1 R2.2 | length 2.1
  TopLayer w0.5: R2.2 18.801,43.287 LED2.1
NetP1_2: P1.2 R13.2 | length 2.3
  TopLayer w0.4: R13.2@5.447,51.625 5.496,51.576 P1.2@7.738,51.576
NetQ6_1: Q6.1 R11.2 | length 2.1
  BottomLayer w0.4: R11.2 7.788,51.675 Q6.1
NetQ6_3: Q6.3 R7.1 U3.2 U3.3 | length 11
  BottomLayer w0.4: Q6.3 11.525,52.625 12,53.1 16,53.1 ; U3.3 16.44,53.54 16,53.1 ; U3.2 17.71,53.685 17.125,53.1 16,53.1
NetR4_2: R4.2 U3.6 | length 2.9
  BottomLayer w0.4: R4.2 16.44,61.523 U3.6
NetR8_2: R8.2 U6.8 | length 2.1
  TopLayer w0.3: U6.8 v2(3.475,56.725)
  BottomLayer w0.3: v2(3.475,56.725) 3.488,56.712 R8.2
NetR17_2: R17.2 U3.7 | length 2.7
  BottomLayer w0.4: R17.2 17.71,62.039 U3.7
NetR20_1: R20.1 U15.12 | length 4
  TopLayer w0.3: v2(6.275,15.25) 6.544,15.52 U15.12
  BottomLayer w0.3: R20.1@4.325,16.178 4.325,15.625 4.7,15.25 v2(6.275,15.25)
NetR23_1: R23.1 U1.10 | length 7.7
  TopLayer w0.3: R23.1 2.849,31.274 3.875,32.3 6.9,32.3 7.33,31.87 U1.10
NetR25_1: R25.1 U15.11 | length 2.5
  TopLayer w0.3: U15.11 7.194,15.63 v2(7.575,15.25)
  BottomLayer w0.3: v2(7.575,15.25) 8.175,15.85 R25.1@8.175,16.153
PH-CMP: J2.1 U15.8 | length 71.3
  TopLayer w0.3: 4.475,8.975 4.475,6.025 3.95,5.5 1.4,5.5 0.925,5.025 0.925,2.625 1.9,1.65 7.25,1.65 8.1,2.5 8.1,8.95 8.494,9.344 U15.8 8.494,11.781 7.95,12.325 5.625,12.325 4.6,11.3
  TopLayer w0.4: U15.8 9.9,10.075
  TopLayer w0.8: 9.9,10.075 12.6,7.375 J2.1
  BottomLayer w0.3: 4.525,9 4.525,6.1 3.925,5.5 1.475,5.5 0.925,4.95 0.925,2.625 1.925,1.625 7.25,1.625 8.1,2.475 8.1,8.95 8.5,9.35 v2(8.5,11.275) 8.5,11.775 7.95,12.325 5.625,12.325 4.6,11.3
PH-INP: J1.2 U15.5 | length 6.5
  TopLayer w0.4: J1.2@5.95,3.825 5.95,8.5 6.544,9.094 U15.5
RS485+: J4.1 R4.1 R5.2 R18.1 U9.2 | length 10.4
  BottomLayer w0.3: J4.1 13.05,68.1 13.05,66.375 13.75,65.675 U9.2 14.128,64.19 R5.2 14.026,64.087 R18.1
  BottomLayer w0.5: R4.1 R5.2@14.038,64.025
RS485-: J4.2 R5.1 R17.1 R19.1 U9.1 | length 10.1
  TopLayer w0.3: v1(16.475,64.15) 16.475,63.912 R19.1
  BottomLayer w0.3: J4.2 13.8,69.16 13.8,66.9 14.125,66.575 14.708,66.575 15.608,65.675 U9.1 15.587,65.228 15.587,64.124 R5.1
  BottomLayer w0.5: R5.1 15.587,64.074 17.199,64.074 R17.1
RST#: C8.1 P2.3 R14.2 U2.4 | length 19.5
  TopLayer w0.3: P2.3@2,46 2.65,45.35 4.874,45.35 6.549,43.675 12.125,43.675 v2(12.65,44.2)
  BottomLayer w0.3: U2.4 12.275,46.95 13.15,46.075 13.15,45.45 13.6,45 R14.2@13.6,44.172 ; v2(12.65,44.2) 12.678,44.172 R14.2@13.6,44.172 ; C8.1 14.891,44.172 R14.2@13.6,44.172
RX485: U2.10
SCK1: R10.2 U1.4 U2.12 | length 13.1
  TopLayer w0.3: R10.2 10.501,42.024 11.14,41.385 U1.4 11.125,39.26 v1(11.125,37.2)
  BottomLayer w0.3: U2.12 9.075,42.1 11.125,40.05 v1(11.125,37.2)
SPI_CS: U1.14 U5.3 | length 14.9
  TopLayer w0.3: U5.3 v2(9.809,21.691) ; v2(12.4,32.05) 12.4,30.014 U1.14
  BottomLayer w0.3: v2(9.809,21.691) 10.225,22.108 10.225,25.8 12.4,27.975 v2(12.4,32.05)
SPI_DIN: U1.12 U5.16 | length 5.6
  TopLayer w0.3: v2(7.975,27.2) 8.531,26.644 U5.16 ; v2(9.85,27.975) 9.85,29.984 U1.12
  BottomLayer w0.3: v2(7.975,27.2) 9.125,27.2 9.85,27.925 v2(9.85,27.975)
SPI_DOUT: U1.11 U5.15 | length 4.1
  TopLayer w0.25: U1.11 8.6,27.825 9.181,27.244 U5.15
SPI_SCLK: U1.13 U5.1 | length 10.8
  TopLayer w0.3: U5.1 8.525,20.295 v2(8.525,21.675) ; v2(11.14,28.015) U1.13
  BottomLayer w0.3: v2(8.525,21.675) 9.525,22.675 9.525,26.4 v2(11.14,28.015)
SSEL1: R12.2 U1.3 U2.11 | length 19.6
  TopLayer w0.25: R12.2 3.961,36.175 11.925,36.175 12.4,36.65 v1(12.4,37.15) 12.4,39.265 U1.3
  BottomLayer w0.25: U2.11 9.575,42.65 12.4,39.825 v1(12.4,37.15)
TP+: J2.3 R3.1 R21.2 U5.11 | length 47.8
  TopLayer w0.3: U5.11 11.781,27.381 12.05,27.65 13.375,27.65 13.875,27.15 13.875,26.525 14.675,25.725 17.525,25.725
  TopLayer w0.5: 17.525,25.725 18.35,25.725 19.225,24.85 19.225,13 16.95,10.725 16.95,6.475 J2.3
  BottomLayer w0.5: R3.1 18.374,13.764 R21.2 18.412,13.212 16.875,11.675 16.875,6.55 J2.3
TX485: U2.9
VCC3.3: C1.1 C3.2 C4.1 C10.1 C11.1 C12.1 C13.1 CA1.1 FB7.2 J3.1 P2.1 P3V3.1 R1.1 R2.1 R6.1 R7.2 R9.1 R10.1 R12.1 R13.1 R14.1 U1.1 U2.1 U2.6 U2.19 U2.27 U3.8 | length 64.7
  TopLayer w0.3: P2.1 2.875,41.8 7.4,41.8 7.624,42.024 R10.1 R10.1@8.338,42.024 ; v2(12.1,49.1) v2(12.1,49.1) C10.1 ; v2(12.2,45.65) 12.974,46.424 C11.1
  TopLayer w0.4: C12.1@4.05,49.886 C12.1 4.038,48.512 v2(4.125,48.425) ; R13.1@4.05,51.625 v1(4.05,52.375) ; v2@4.138,44.413 v2(4.175,44.45) ; v2(16.726,41.026) R2.1
  TopLayer w0.5: R12.1 1.988,40.913 P2.1 ; C13.1@4.138,43.324 v2@4.138,44.413 ; P3V3.1@13.587,55.125 R1.1 R1.1@13.587,57.676 ; U1.1 15.751,38.474 C1.1 C3.2 v1(16.524,36.726)
  TopLayer w1: P3V3.1 14.275,54.575 FB7.2
  BottomLayer w0.3: v2(4.125,48.425) 4.1,48.45 U2.27 ; v2(4.175,44.45) U2.19 ; U2.6 11.925,45.95 12.2,45.675 v2(12.2,45.65) ; U2.1 11.7,48.45 v2@12.075,48.825
  BottomLayer w0.4: R7.2 13.065,51.613 13.327,51.875 v2(14.125,51.875) ; U3.8 19,59.92 C4.1 v1(20.013,62.538)
  BottomLayer w0.5: R6.1 1.988,40.913 P2.1 ; CA1.1 16.489,36.761 v1(16.524,36.726)
  BottomLayer w0.6: v1(13.549,41.726) R14.1
  BottomLayer w0.8: J3.1 2.05,66.95 3.65,65.35 3.65,58.5 1.825,56.675 1.825,54.1 3.55,52.375 v1(4.05,52.375)
VDD_ISO: C2.1 C6.1 C14.1 C25.1 CA2.1 FB1.1 R23.2 U1.16 U5.13 U7.3 U15.1 U15.14 | length 19.6
  TopLayer w0.3: v2(3.75,15) 4.85,15 5.244,15.395 U15.14 ; U5.13 10.481,24.844 v2(10.925,24.4)
  TopLayer w0.4: v2(2.825,11.5) 2.825,10.9 3.65,10.075 U15.1
  TopLayer w0.5: v1(2.849,27.851) R23.2 ; U1.16 15.846,30.004 v1(16.651,29.199) C2.1
  BottomLayer w0.4: v2(10.925,24.4) 10.925,24.3 C14.1@11.675,23.55
  BottomLayer w0.5: C25.1 2.349,11.976 v2(2.825,11.5) ; FB1.1@4.549,20.975 v1(5.475,20.975) ; U7.3 16.001,25.437 C6.1 v1(19.126,26.374) ; CA2.1 16.449,29.401 v1(16.651,29.199)
VREF: C33.1 C35.1 FB2.2 U5.9 U15.9 | length 18.4
  TopLayer w0.35: U15.9 11.989,16.475 C33.1 C33.1@13.387,17.975 ; U5.9 13.081,25.194 13.9,24.375 C35.1@15.875,24.375
  TopLayer w0.5: C33.1 13.438,18.413 v1(14.4,19.375) 15.463,20.438 15.463,23.963 C35.1@15.875,24.375
  BottomLayer w0.5: v1(14.4,19.375) 14.939,19.375 FB2.2
pads on no net: J5.1 J5.2 J5.3 J6.1 J6.2 J6.3 U1.7 U2.7 U2.15 U2.16 U2.20 U2.24 U2.32 U2.33 U2.34 U5.2 U5.4 U6.7 U6.9 U15.2 U15.3 U15.7

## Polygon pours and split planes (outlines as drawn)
GND_ISO on TopLayer "BottomLayer-No Net" (hatched 90Degree grid 0.3 track 0.3, remove dead copper, pour order 10): 0.7,33.4 21.125,33.4 21.125,11.95 21.075,11.9 13.575,11.9 11.1,14.375 0.7,14.375
GND on TopLayer "BottomLayer-No Net" (hatched 90Degree grid 0.3 track 0.3, remove dead copper, pour order 4): 0.275,70.575 20.85,70.575 20.95,70.675 20.95,34.625 20.9,34.575 0.675,34.575 0.325,34.925
GND_ISO on BottomLayer "BottomLayer-No Net" (hatched 90Degree grid 0.3 track 0.3, remove dead copper, pour order 8): 0.65,33.325 21.25,33.325 21.25,12.075 21.3,12.025 13.475,12.025 11.275,14.225 11,14.5 0.6,14.5
GND on BottomLayer "BottomLayer-No Net" (hatched 90Degree grid 0.3 track 0.3, remove dead copper, pour order 6): 0.625,70.85 21.2,70.85 21.275,70.775 21.275,34.75 21.125,34.6 0.975,34.6 0.8,34.775
GND_ISO on GND (split plane): 21.49,0.56 8.025,0.56 8.025,11.6 7.7,11.925 6.525,11.95 5.925,11.95 5.5,11.525 5.5,8.95 3.825,7.275 0.505,7.275 0.505,33.523 21.49,33.523
GND on GND (split plane): 21.49,34.327 0.505,34.327 0.505,53.498 9.075,53.498 9.14,53.506 9.201,53.532 9.253,53.572 10.678,54.997 10.696,55.019 10.718,55.049 10.744,55.11 10.752,55.175 10.752,61.946 11.504,62.698 17,62.698 17.065,62.706 17.126,62.732 17.178,62.772 17.218,62.824 17.244,62.885 17.252,62.95 17.244,63.015 17.218,63.076 17.178,63.128 17.126,63.168 17.065,63.194 17,63.202 11.4,63.202 11.335,63.194 11.274,63.168 11.222,63.128 10.322,62.228 10.282,62.176 10.256,62.115 10.248,62.05 10.248,55.279 8.971,54.002 0.505,54.002 0.505,73.54 21.49,73.54
+24V on PWR (split plane): 21.49,64.052 10.575,64.052 10.51,64.044 10.449,64.019 10.397,63.978 10.357,63.926 10.331,63.865 10.323,63.8 10.323,57.005 9.671,56.352 6.274,56.352 6.209,56.344 6.148,56.319 6.096,56.278 6.022,56.205 5.982,56.152 5.956,56.092 5.948,56.026 5.948,53.577 0.505,53.577 0.505,73.54 21.49,73.54
NetC23_1 on PWR (split plane): 12.798,62.925 12.798,56.23 10.146,53.577 6.452,53.577 6.452,55.848 9.775,55.848 9.84,55.857 9.901,55.882 9.953,55.922 10.753,56.722 10.793,56.774 10.819,56.835 10.827,56.9 10.827,63.548 12.798,63.548
VCC3.3 on PWR (split plane): 21.49,34.327 0.505,34.327 0.505,53.073 10.275,53.073 10.34,53.082 10.401,53.107 10.453,53.147 10.493,53.199 10.502,53.221 13.154,55.873 13.176,55.882 13.228,55.922 13.268,55.974 13.294,56.035 13.302,56.1 13.302,63.548 21.49,63.548
VDD_ISO on PWR (split plane): 21.49,0.56 8.025,0.56 8.025,11.625 7.7,11.95 5.875,11.95 5.5,11.575 5.5,8.9 3.85,7.25 0.505,7.25 0.505,33.523 21.49,33.523

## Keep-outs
KeepOutLayer:
  lines w0.3: 8.8,-0.275 8.8,8.1 cw(c9.413,7.908) 10.025,8.1 ; 10.05,-0.325 10.05,8.1
  lines w0.5: -0.006,0.05 -0.006,74.05 22,74.05 22,0.05 -0.006,0.05

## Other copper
TopLayer:
  pour cut-out: 6.425,60.575 10.4,60.575 10.4,56.525 6.45,56.525 6.425,56.55
GND (plane layer: these items are gaps in the copper):
  pour cut-out: 6.525,11.95 5.925,11.95 5.5,11.525 5.5,8.95 3.825,7.275 -0.775,7.275 -0.825,7.225 -0.825,-0.95 -0.75,-1.025 7.95,-1.025 8.025,-0.95 8.025,11.6 7.7,11.925
  lines w0.5: 0.025,53.75 9.075,53.75 10.5,55.175 10.5,62.05 11.4,62.95 17,62.95
  lines w0.8: -0.025,33.925 21.875,33.925
PWR (plane layer: these items are gaps in the copper):
  pour cut-out: 5.875,11.95 5.5,11.575 5.5,8.9 3.85,7.25 -0.75,7.25 -0.775,7.275 -0.775,-1 -0.725,-1.05 7.975,-1.05 8.025,-1 8.025,11.625 7.7,11.95
  lines w0.5: 0.175,53.325 6.2,53.325 ; 10.275,53.325 6.2,53.325 ; 13.05,56.1 13.05,63.8 ; 13.05,62.925 13.05,56.125 10.25,53.325 6.2,53.325 ; 22.125,63.8 13.05,63.8 ; 6.2,53.325 6.2,56.026 6.274,56.1 9.775,56.1 10.575,56.9 10.575,63.8 13.05,63.8
  lines w0.8: -0.025,33.925 22.1,33.925

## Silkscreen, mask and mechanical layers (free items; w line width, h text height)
TopOverlay:
  lines w0.3: 1.125,0.975 14.375,0.975 14.375,13.025 1.125,13.025 1.125,0.975
  text "3V3 0V 24V  A  B  E" at 1.1,67.125 h1
  text "SPSensor_V0.5" at 10.375,13.4 h1
  text "GUA INP" at 1.475,5.975 h1
  text "VCM T- T+" at 10.175,5.875 h1
Mechanical1:
  lines w0.3: -4.65,71.55 22.875,71.55 ; -2.006,1.05 29.575,1.05 ; -0.075,69 4.175,69 ; 0.006,4.125 0.006,78.075 ; 15.55,7.05 21.425,7.05 ; 19.5,-2.85 19.5,73.275

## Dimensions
-4.65,71.55 to -0.075,69 on Mechanical1
-0.006,4.75 to 21.975,-0.5 on Mechanical1
22,74.05 to 22,0.05 on Mechanical1
19.525,-2.725 to 21.975,-1.525 on Mechanical1
29.475,0.025 to 21.425,7.05 on Mechanical1
-4.675,74.1 to -0.1,71.55 on Mechanical1
14.375,12.758 to 1.103,12.536 on Mechanical1
13.889,1.029 to 13.95,13.025 on Mechanical1
0.786,12.971 to 0.375,10.45 on Mechanical1
14.9,13.024 to 14.883,7.05 on Mechanical1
